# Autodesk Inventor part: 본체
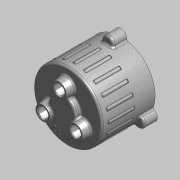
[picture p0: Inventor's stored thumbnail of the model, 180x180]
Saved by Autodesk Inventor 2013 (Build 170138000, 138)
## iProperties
Created: 2015-11
Part Number: 본체
Document SubType Name: 모델링
Designer: mdu
Material: 일반
Density: 1 g/cm^3
변환 표준: STEP AP214IS
파일 이름: C:\Users\SeoGD\Desktop\?쒗뿕\紐몄껜.stp
전처리기: Build: 253, Release: 2010 SP1 - Date: Wed 07/29/2009
전송 단위: 밀리미터
불확실성: 0.01
Author: mdu
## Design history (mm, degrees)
sketch "스케치2"
  geometry: C1 r 50 at (0, 0); 1 further point
  constraints: 1 centre point, 1 coincident
  dimensions: "d9" = 100 diameter of C1
extrude "돌출2" new body sketch "스케치2" distance "d10" = 78.5; taper "d11" = 0 deg
feature "쉘1" dims "d12" = 5
sketch "스케치3" dims "d13" = 55
  geometry: C1 r 7.5 at (0, 27.5); C2 r 12.5 at (0, 27.5); 2 further points
  constraints: 2 centre point, 2 coincident, 2 vertical alignment, 2 other
  dimensions: "d14" = 15 diameter of C1; "d15" = 25 diameter of C2
extrude "돌출3" join sketch "스케치3" distance "d16" = 12; taper "d17" = -10 deg
hole "구멍2" diameter "d20" = 15; stored, may be unused: countersink angle "d24" = 90 deg, drill point angle "d26" = 118 deg; dims "d18" = 10, "d19" = 10, "d21" = 6, "d22" = 4, "d23" = 2, "d25" = 15
chamfer "모따기1" distance "d27" = 1; stored, may be unused: second distance "d28" = 2, angle "d29" = 45 deg
sketch "스케치4"
  geometry: L1 (0, 0)-(0, 86.5); L2 (0, 68.5)-(13.16, 68.5); L3 (-45, 73.5)-(45, 73.5) reference; L4 (-50, 78.5)-(50, 78.5) reference; L5 (13.16, 68.5)-(14.5, 73.5); L6 (20, 78.5)-(20, 86.5); L7 (20, 86.5)-(0, 86.5); L8 (20, 78.5)-(14.5, 73.5)
  constraints: 12 end point, 3 point on line, 2 perpendicular, 1 vertical
  dimensions: "d34" = 40 diameter of L6 L1; "d35" = 105 deg angle of L5 L3; "d36" = 5 distance between parallel lines of L2 L3; "d37" = 8 distance between parallel lines of L7 L4; "d51" = 29 diameter of L5.end L1
revolve "회전1" sketch "스케치4" stored, may be unused: angle "d38" = 90 deg
hole "구멍3" diameter "d41" = 15; stored, may be unused: countersink angle "d45" = 90 deg, drill point angle "d47" = 0 deg; dims "d39" = 10, "d40" = 10, "d42" = 6, "d43" = 22, "d44" = 13, "d46" = 15
chamfer "모따기2" distance "d48" = 1; stored, may be unused: second distance "d49" = 2, angle "d50" = 45 deg
fillet "모깎기1" dims "d52" = 3
fillet "모깎기2" dims "d53" = 3, "d72" = 0.2
sketch "스케치5"
  geometry: A1 r 50 centre (0, 0) between (50, 0) and (-8.074, 49.344) reference; A2 r 8.5 centre (0, 52) between (8.074, 49.344) and (-8.074, 49.344); 1 further point
  constraints: 5 point on circle, 1 centre point, 1 horizontal alignment
  dimensions: "d54" = 90 deg dimension on point (0, 0) A2.centre A1.start; "d55" = 52 distance of A2.centre point (0, 0); "d56" = 17 diameter of A2
extrude "돌출4" join sketch "스케치5" distance "d57" = 20; taper "d58" = 0 deg
fillet "모깎기3" dims "d59" = 3
hole "구멍4" diameter "d62" = 4.134; stored, may be unused: countersink angle "d66" = 90 deg, drill point angle "d68" = 118 deg; dims "d60" = 10, "d61" = 10, "d63" = 12, "d64" = 22, "d65" = 13, "d67" = 15
sketch "스케치6"
  geometry: C1 r 47 at (0, 0) reference; C2 r 42.5 at (0, 0); 1 further point
  constraints: 1 centre point, 1 coincident, 1 other
  dimensions: "d73" = 85 diameter of C2
feature "엠보싱1" sketch "스케치6" dims "d74" = 0.5, "d75" = 0
node "작업 평면1"
sketch "스케치7"
  geometry: A1 r 50 centre (0, 0) between (5.144, 49.735) and (-5.144, 49.735) reference; A2 r 3 centre (0, 47.916) between (2.204, 49.951) and (-2.204, 49.951); 1 further point
  constraints: 4 point on circle, 1 centre point, 1 vertical alignment
  dimensions: "d77" = 3 radius of A2
extrude "돌출5" join sketch "스케치7" distance "d79" = 38; taper "d80" = 0 deg
fillet "모깎기4" dims "d81" = 1
fillet "모깎기5" dims "d82" = 1
node "솔리드1"
node "솔리드 본체"
node "곡면 본체"
pattern_circular "원형 패턴1" dims "d31" = 360 deg
pattern_circular "원형 패턴2" dims "d70" = 360 deg
pattern_circular "원형 패턴3" dims "d84" = 360 deg
node "솔리드2"
